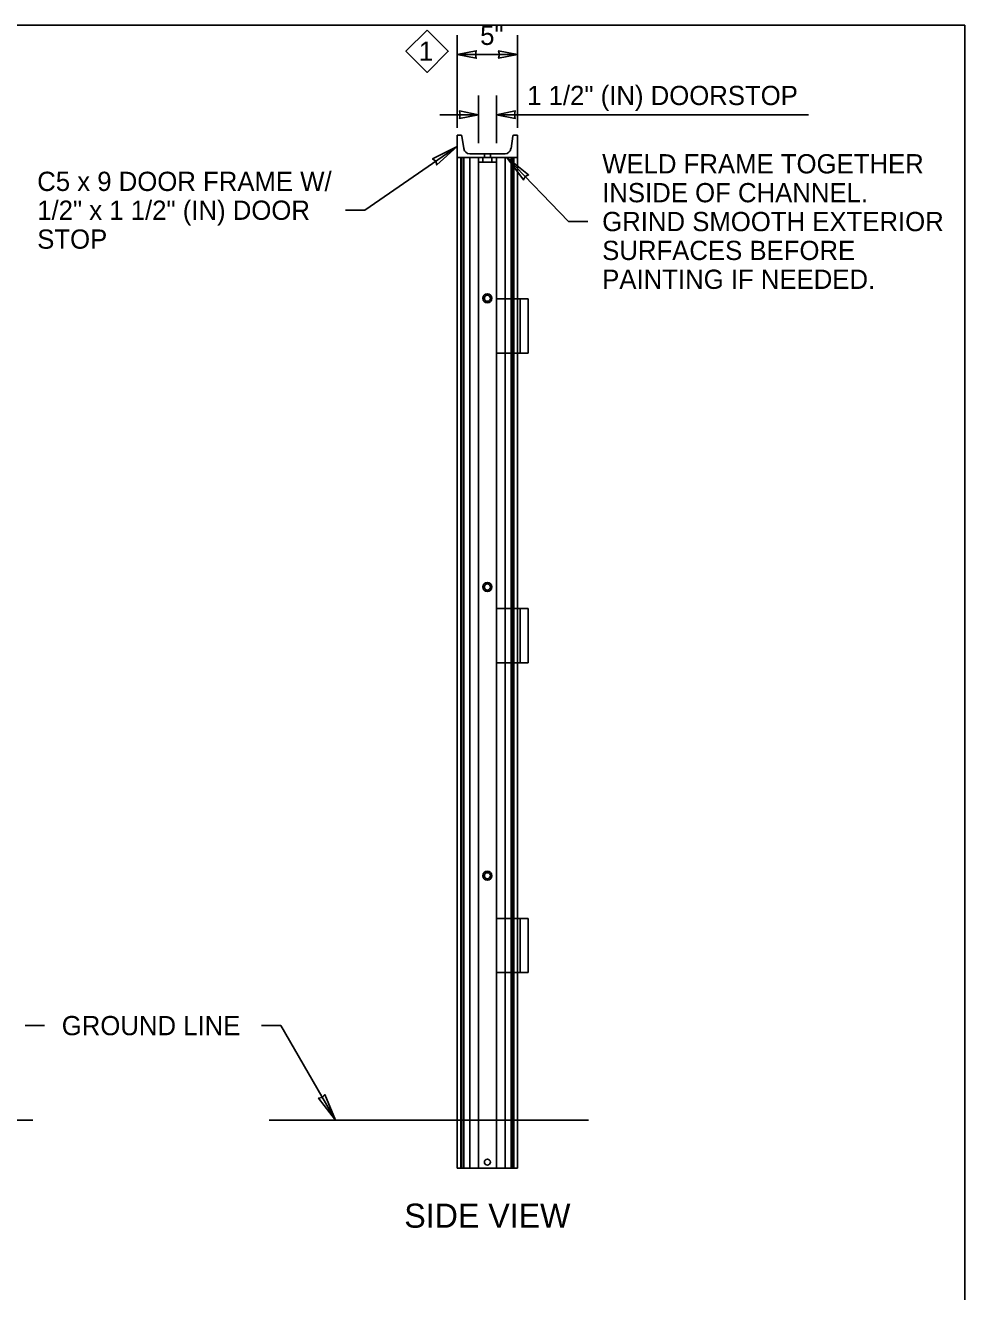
# Model space of a CAD drawing. Extents: x 99862 to 103151, y 100000 to 105076.
# Drawn here: x 102370 to 103151, y 104023 to 105076 of the extents above; entities that cross this region are included whole.
import ezdxf

# ---------------------------------------------------------------- set-up
doc = ezdxf.new("R2010")
doc.units = 0
for name, color, linetype in [('Level 1', 7, 'Continuous'), ('Level 15', 7, 'Continuous'), ('Level 18', 7, 'Continuous'), ('Level 20', 7, 'Continuous'), ('Level 5', 7, 'Continuous'), ('Level 60', 7, 'Continuous')]:
    doc.layers.add(name, color=color, linetype=linetype)

msp = doc.modelspace()

# ---------------------------------------------------------------- linework, layer by layer
at = {"layer": 'Level 1'}
msp.add_line((102572.5, 104165.5), (102838.2, 104165.5), dxfattribs=at)
msp.add_lwpolyline([(99862, 102999.5), (103151, 102999.5), (103151, 105075.5), (99862, 105075.5)], close=True, dxfattribs=at)
at = {"layer": 'Level 15'}
for p, q in [((102729, 105067.2), (102729, 104990.2)), ((102779, 105067.2), (102779, 104990.2)), ((102729, 105051.2), (102779, 105051.2)), ((102746.5, 105017.2), (102746.5, 104977.5)), ((102761.5, 105017.2), (102761.5, 104977.5)), ((102714.5, 105001.2), (102746.5, 105001.2)), ((102761.5, 105001.2), (103021, 105001.2)), ((102729, 104974.9), (102652, 104921.8)), ((102770.3, 104965.5), (102821.5, 104912.4)), ((102652, 104921.8), (102636, 104921.8)), ((102821.5, 104912.4), (102837.5, 104912.4)), ((102369.7, 104244), (102385.7, 104244)), ((102566.2, 104244), (102582.2, 104244)), ((102627.6, 104165.5), (102582.2, 104244))]:
    msp.add_line(p, q, dxfattribs=at)
for points in [[(102729, 105051.2), (102744.7, 105048.1), (102744, 105051.2), (102744.7, 105054.3)], [(102779, 105051.2), (102763.3, 105048.1), (102764, 105051.2), (102763.3, 105054.3)], [(102746.5, 105001.2), (102730.8, 104998.1), (102731.5, 105001.2), (102730.8, 105004.3)], [(102761.5, 105001.2), (102777.2, 104998.1), (102776.5, 105001.2), (102777.2, 105004.3)], [(102729, 104974.9), (102711.9, 104959.5), (102711.1, 104962.5), (102708.5, 104964.4)], [(102770.3, 104965.5), (102788.3, 104951.1), (102785.4, 104949.8), (102784, 104947)], [(102627.6, 104165.5), (102618.7, 104186.7), (102616.7, 104184.3), (102613.6, 104183.7)]]:
    msp.add_lwpolyline(points, close=True, dxfattribs=at)
at = {"layer": 'Level 18'}
for p, q in [((102750.3, 104965.5), (102750.3, 104961.7)), ((102751.5, 104968.7), (102751.5, 104965.5)), ((102756.5, 104968.7), (102756.5, 104965.5)), ((102757.8, 104965.5), (102757.8, 104961.7)), ((102746.5, 104961.7), (102746.5, 104125.5)), ((102761.5, 104961.7), (102761.5, 104125.5)), ((102761.5, 104848.1), (102779, 104848.1)), ((102781.2, 104848.1), (102779, 104848.1)), ((102781.2, 104848.1), (102786.1, 104848.1)), ((102781.2, 104803.1), (102781.2, 104848.1)), ((102786.1, 104848.1), (102787.8, 104848.1)), ((102787.8, 104803.1), (102787.8, 104848.1)), ((102761.5, 104803.1), (102779, 104803.1)), ((102781.2, 104803.1), (102779, 104803.1)), ((102781.2, 104803.1), (102787.8, 104803.1)), ((102761.5, 104590.6), (102779, 104590.6)), ((102781.2, 104590.6), (102779, 104590.6)), ((102781.2, 104590.6), (102786.1, 104590.6)), ((102781.2, 104545.6), (102781.2, 104590.6)), ((102786.1, 104590.6), (102787.8, 104590.6)), ((102787.8, 104545.6), (102787.8, 104590.6)), ((102761.5, 104545.6), (102779, 104545.6)), ((102781.2, 104545.6), (102779, 104545.6)), ((102781.2, 104545.6), (102787.8, 104545.6)), ((102761.5, 104333.1), (102779, 104333.1)), ((102781.2, 104333.1), (102779, 104333.1)), ((102781.2, 104333.1), (102786.1, 104333.1)), ((102781.2, 104288.1), (102781.2, 104333.1)), ((102786.1, 104333.1), (102787.8, 104333.1)), ((102787.8, 104288.1), (102787.8, 104333.1)), ((102761.5, 104288.1), (102779, 104288.1)), ((102781.2, 104288.1), (102779, 104288.1)), ((102781.2, 104288.1), (102787.8, 104288.1)), ((102779, 104165.5), (102779, 104125.5)), ((102729, 104125.5), (102779, 104125.5))]:
    msp.add_line(p, q, dxfattribs=at)
for points in [[(102746.5, 104965.5), (102746.5, 104961.7), (102761.5, 104961.7), (102761.5, 104965.5)], [(102729, 104165.5), (102729, 104125.5)], [(102731.9, 104165.5), (102731.9, 104125.5)], [(102732.9, 104165.5), (102732.9, 104125.5)], [(102734.4, 104165.5), (102734.4, 104125.5)], [(102739.3, 104165.5), (102739.3, 104125.5)], [(102768.7, 104165.5), (102768.7, 104125.5)], [(102773.7, 104165.5), (102773.7, 104125.5)], [(102775.1, 104165.5), (102775.1, 104125.5)], [(102776.1, 104165.5), (102776.1, 104125.5)]]:
    msp.add_lwpolyline(points, dxfattribs=at)
for centre, radius in [((102754, 104848.6), 3.75), ((102754, 104608.6), 3.75), ((102754, 104368.6), 3.75), ((102754, 104130.5), 2.5)]:
    msp.add_circle(centre, radius, dxfattribs=at)
at = {"layer": 'Level 20'}
msp.add_lwpolyline([(102703.8, 105071.5), (102721.4, 105054), (102703.8, 105036.4), (102686.3, 105054)], close=True, dxfattribs=at)
at = {"layer": 'Level 5'}
for p, q in [((102731.9, 104984.3), (102729, 104984.3)), ((102729, 104984.3), (102729, 104965.5)), ((102734.4, 104973), (102732.9, 104983.4)), ((102775.1, 104983.4), (102773.7, 104973)), ((102779, 104984.3), (102776.1, 104984.3)), ((102779, 104965.5), (102779, 104984.3)), ((102731.9, 104965.5), (102729, 104965.5)), ((102729, 104165.5), (102729, 104965.5)), ((102731.9, 104965.5), (102776.1, 104965.5)), ((102731.9, 104165.5), (102731.9, 104965.5)), ((102732.9, 104165.5), (102732.9, 104965.5)), ((102734.4, 104165.5), (102734.4, 104965.5)), ((102768.7, 104968.7), (102739.3, 104968.7)), ((102739.3, 104165.5), (102739.3, 104965.5)), ((102768.7, 104165.5), (102768.7, 104965.5)), ((102773.7, 104165.5), (102773.7, 104965.5)), ((102775.1, 104165.5), (102775.1, 104965.5)), ((102779, 104965.5), (102776.1, 104965.5)), ((102776.1, 104165.5), (102776.1, 104965.5)), ((102779, 104165.5), (102779, 104965.5)), ((102376, 104165.5), (102276.6, 104165.5)), ((102731.9, 104165.5), (102729, 104165.5)), ((102731.9, 104165.5), (102732.9, 104165.5)), ((102734.4, 104165.5), (102732.9, 104165.5)), ((102739.3, 104165.5), (102734.4, 104165.5)), ((102768.7, 104165.5), (102739.3, 104165.5)), ((102761.5, 104165.5), (102761.5, 104165.4)), ((102768.7, 104165.5), (102773.7, 104165.5)), ((102775.1, 104165.5), (102773.7, 104165.5)), ((102776.1, 104165.5), (102775.1, 104165.5)), ((102779, 104165.5), (102776.1, 104165.5))]:
    msp.add_line(p, q, dxfattribs=at)
for centre in [(102754, 104848.6), (102754, 104608.6), (102754, 104368.6)]:
    msp.add_circle(centre, 2.5, dxfattribs=at)
for centre, radius, start, end in [((102731.9, 104983.3), 1, 7.876, 90), ((102776.1, 104983.3), 1, 90, 172.124), ((102739.3, 104973.7), 5, 187.876, 270), ((102768.7, 104973.7), 5, 270.0003, 352.124)]:
    msp.add_arc(centre, radius, start, end, dxfattribs=at)
at = {"layer": 'Level 60'}
msp.add_line((103151, 105075.5), (103151, 105075.5), dxfattribs=at)

# ---------------------------------------------------------------- texts
at = {"layer": 'Level 20'}
for s, p in [('5"', (102748, 105059.2)), ('GROUND LINE', (102400, 104236))]:
    msp.add_text(s, height=16, rotation=360, dxfattribs=at).set_placement(p)
for s, height, p in [('1', 16, (102697, 105046)), ('1 1/2" (IN) DOORSTOP', 16, (102787.1, 105009.2)), ('WELD FRAME TOGETHER', 16, (102849.5, 104952.4)), ('C5 x 9 DOOR FRAME W/', 16, (102379.6, 104937.8)), ('INSIDE OF CHANNEL.', 16, (102849.5, 104928.4)), ('1/2" x 1 1/2" (IN) DOOR', 16, (102379.6, 104913.8)), ('GRIND SMOOTH EXTERIOR', 16, (102849.5, 104904.4)), ('STOP', 16, (102379.6, 104889.8)), ('SURFACES BEFORE', 16, (102849.5, 104880.4)), ('PAINTING IF NEEDED.', 16, (102849.5, 104856.4)), ('SIDE VIEW', 20, (102684.9, 104076))]:
    msp.add_text(s, height=height, dxfattribs=at).set_placement(p)

doc.saveas('drawing.dxf')
